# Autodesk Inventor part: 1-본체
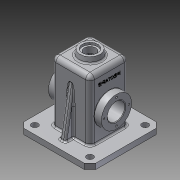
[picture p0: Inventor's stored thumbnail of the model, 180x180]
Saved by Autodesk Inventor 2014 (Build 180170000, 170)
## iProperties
Created: 2016-02
Part Number: 1-본체
Material: 알루미늄 6061
Document SubType Name: Modeling
Designer: D.Y.KIM
Density: 2.71 g/cm^3
Appearance: 알루미늄 - 평지
Mass: 926.895 g
Surface Area: 1038.71 cm^2
Volume: 342.028 cm^3
Author: D.Y.KIM
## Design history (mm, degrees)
sketch "스케치1"
  geometry: L1 (0, 0)-(-65, 0); L2 (-65, 0)-(-65, 10); L3 (-65, 10)-(0, 10); L4 (0, 10)-(0, 0)
  constraints: 8 end point, 2 parallel, 1 horizontal, 1 perpendicular
  dimensions: "d0" = 130 diameter of L2 L4; "d1" = 10 distance of L1.end L2.end
extrude "돌출1" new body sketch "스케치1" stored distance "d2" = 130; taper "d3" = 0 deg
chamfer "모따기1" distance "d4" = 10; stored, may be unused: second distance "d5" = 2, angle "d6" = 45 deg
sketch "스케치2"
  geometry: L1 (55, 0)-(0, 0) reference; L2 (0, 130)-(55, 130) reference; L3 (0, 130)-(0, 0) reference; 3 further points
  dimensions: "d7" = 15 distance from line of point (50, 15) L1; "d8" = 15 distance from line of L2 point (50, 115); "d9" = 50 horizontal distance of L1.end point (50, 15); "d10" = 50 distance from line of L3 point (50, 115)
hole "구멍1" sketch "스케치2" at (50, 15), (50, 115) diameter "d11" = 12; stored, may be unused: countersink angle "d15" = 90 deg, drill point angle "d17" = 118 deg; dims "d12" = 6, "d13" = 4, "d14" = 2, "d16" = 12
sketch "스케치3"
  geometry: L1 (-100, 90)-(-30, 90); L2 (-30, 90)-(-30, 20); L3 (-30, 20)-(-100, 20); L4 (-100, 20)-(-100, 90); 3 further points
  constraints: 8 end point, 2 midpoint, 2 parallel, 1 horizontal, 1 horizontal alignment, 1 perpendicular, 1 vertical alignment
  dimensions: "d18" = 70 distance of L1.start L1.end; "d19" = 70 distance of L3.end L1.start
extrude "돌출2" join sketch "스케치3" distance "d20" = 110; taper "d21" = 0 deg
feature "쉘1" dims "d22" = 10, "d23" = 5
fillet "모깎기1" dims "d24" = 8
fillet "모깎기2" dims "d25" = 3
fillet "모깎기3" dims "d26" = 8
fillet "모깎기4" dims "d27" = 3
sketch "스케치4"
  geometry: L1 (-35, 10)-(-35, 112) reference; L2 (-44, 10)-(-56, 10) reference; L3 (35, 112)-(35, 10) reference; L4 (56, 10)-(44, 10) reference; L5 (-35, 95.069)-(-50, 10); L6 (35, 95.069)-(50, 10); L7 (65, 0)-(65, 10) reference; L8 (-65, 10)-(-65, 0) reference; L9 (-50, 10)-(-35, 10); L10 (-35, 95.069)-(-35, 10); L11 (35, 95.069)-(35, 10); L12 (50, 10)-(35, 10); 1 further point
  constraints: 12 end point, 3 perpendicular, 2 midpoint, 2 point on line, 1 parallel
  dimensions: "d28" = 10 deg angle of L6 L7; "d29" = 10 deg angle of L5 L8
extrude "돌출3" join sketch "스케치4" stored distance "d30" = 10; taper "d31" = 0 deg
node "작업 평면1"
sketch "스케치5"
  geometry: L1 (55, 0)-(-55, 0) reference; C1 r 27.5 at (0, 55); 2 further points
  constraints: 1 centre point, 1 midpoint, 1 vertical alignment
  dimensions: "d33" = 55 diameter of C1; "d34" = 55 distance from line of L1 C1.centre
extrude "돌출4" join sketch "스케치5" stored distance "d35" = 10; taper "d36" = 0 deg
sketch "스케치6"
  geometry: C1 r 27.5 at (55, 27); 1 further point
  constraints: 1 centre point, 1 horizontal alignment
  dimensions: "d37" = 55 diameter of C1; "d38" = 55 distance of point (0, 27) C1.centre
extrude "돌출5" join sketch "스케치6" distance "d39" = 7; taper "d40" = -45 deg
hole "구멍2" diameter "d43" = 32; stored, may be unused: countersink angle "d47" = 90 deg, drill point angle "d49" = 0 deg; dims "d44" = 6, "d45" = 4, "d46" = 2, "d48" = 48, "d50" = 10, "d51" = 10
sketch "스케치7"
  geometry: C1 r 27.5 at (0, 0) reference; 2 further points
  constraints: 1 horizontal alignment
  dimensions: "d52" = 22.5 distance of point (-22.5, 0) C1.centre
hole "구멍3" sketch "스케치7" at (-22.5, 0) diameter "d53" = 3.242; stored, may be unused: countersink angle "d57" = 90 deg, drill point angle "d59" = 118 deg; dims "d54" = 8, "d55" = 4, "d56" = 2, "d58" = 10
fillet "모깎기5" dims "d63" = 0.5
chamfer "모따기2" distance "d64" = 1; stored, may be unused: second distance "d65" = 2, angle "d66" = 45 deg
sketch "스케치8"
  geometry: C1 r 20 at (-65, 55); 1 further point
  constraints: 1 centre point, 1 coincident
  dimensions: "d67" = 40 diameter of C1
extrude "돌출6" join sketch "스케치8" distance "d68" = 10; taper "d69" = -10 deg
hole "구멍4" diameter "d72" = 21; stored, may be unused: countersink angle "d76" = 90 deg, drill point angle "d78" = 118 deg; dims "d70" = 10, "d71" = 10, "d73" = 8, "d74" = 28, "d75" = 4, "d77" = 30
sketch "스케치9"
  geometry: L1 (12.188, 6.261)-(12.188, 47.739); L2 (12.188, 47.739)-(11.812, 47.739); L3 (11.812, 47.739)-(11.812, 6.261); L4 (11.812, 6.261)-(12.188, 6.261); L5 (102, 62)-(0, 62) reference; L6 (-18, 8.763)-(-18, 45.237) reference; 3 further points
  constraints: 2 midpoint, 2 other
  dimensions: "d79" = 35 distance from line of L5 point (12.188, 27); "d80" = 30 distance from line of L6 point (12, 47.739)
feature "엠보싱1" sketch "스케치9" dims "d0" = 130, "d1" = 10, "d81" = 0.5, "d82" = 0
fillet "모깎기6" dims "d83" = 3
fillet "모깎기7" dims "d84" = 3
fillet "모깎기8" dims "d85" = 3
fillet "모깎기9" dims "d86" = 3
node "솔리드1"
mirror "대칭1"
pattern_circular "원형 패턴1" dims angle "d61" = 360 deg
mirror "대칭2"
other parameters: "d32" = 48
